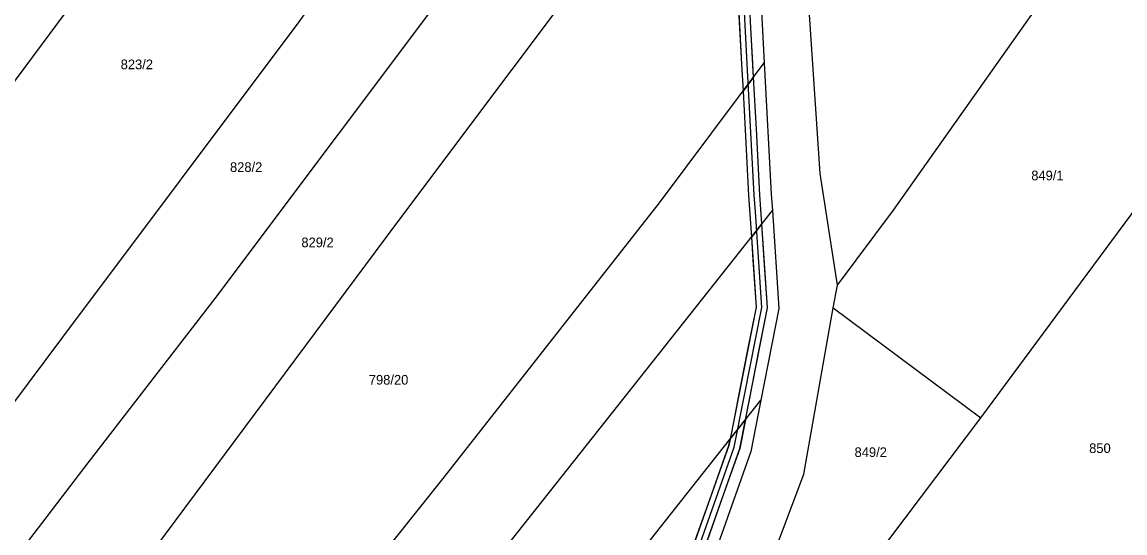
# Model space of a CAD drawing. Extents: x -7483133 to -743907, y -11317770 to -1129777.
# Drawn here: x -747703.2 to -747509.1, y -1131590 to -1131500 of the extents above; entities that cross this region are included whole.
import ezdxf

# ---------------------------------------------------------------- set-up
doc = ezdxf.new("R2010")
doc.units = 0
for name, color, linetype in [('_TRASA_vedení kabelu_CEZ', 7, 'Continuous'), ('DZ_DO_ZPF', 7, 'Continuous'), ('Hranice parcel', 7, 'Continuous'), ('hranice VB', 7, 'Continuous'), ('Parcelní čísla', 7, 'Continuous')]:
    doc.layers.add(name, color=color, linetype=linetype)

msp = doc.modelspace()

# ---------------------------------------------------------------- linework, layer by layer
at = {"layer": '_TRASA_vedení kabelu_CEZ'}
msp.add_lwpolyline([(-747606.66, -1131708.94), (-747603.52, -1131695.37), (-747628.04, -1131689.7), (-747599.97, -1131653.35), (-747599.82, -1131650.35), (-747590.15, -1131609.62), (-747577.85, -1131574.83), (-747576.11, -1131566), (-747573.02, -1131550.26), (-747574.14, -1131533.4), (-747574.33, -1131530.46), (-747575.58, -1131507.34), (-747576.38, -1131492.52)], dxfattribs=at)
at = {"layer": 'DZ_DO_ZPF'}
for points in [[(-747577.28, -1131455.8), (-747579.15, -1131458.26), (-747578.38, -1131473.06), (-747577.37, -1131492.57), (-747576.57, -1131507.4), (-747576.32, -1131512.18), (-747574.45, -1131509.68), (-747574.98, -1131499.88), (-747575.38, -1131492.47), (-747576.39, -1131472.96)], [(-747576.32, -1131512.18), (-747575.95, -1131518.96), (-747575.33, -1131530.52), (-747574.85, -1131537.87), (-747573, -1131535.54), (-747573.34, -1131530.4), (-747573.96, -1131518.84), (-747574.45, -1131509.68)], [(-747573, -1131535.54), (-747574.85, -1131537.87), (-747574.03, -1131550.19), (-747578.6, -1131573.46), (-747575.89, -1131570.02), (-747572.01, -1131550.32)], [(-747578.6, -1131573.46), (-747575.89, -1131570.02), (-747576.88, -1131575.09), (-747579.96, -1131583.79), (-747583.04, -1131592.5), (-747586.11, -1131601.2), (-747589.19, -1131609.9), (-747591.6, -1131620.05), (-747594.01, -1131630.2), (-747596.42, -1131640.34), (-747598.83, -1131650.49), (-747598.98, -1131653.55), (-747626.3, -1131689.08), (-747628.4, -1131688.54), (-747615.37, -1131671.66), (-747608.16, -1131662.32), (-747600.95, -1131652.99), (-747600.82, -1131650.21), (-747598.39, -1131639.99), (-747595.96, -1131629.77), (-747591.11, -1131609.34), (-747584.97, -1131591.95), (-747581.89, -1131583.26), (-747578.82, -1131574.56)]]:
    msp.add_lwpolyline(points, close=True, dxfattribs=at)
at = {"layer": 'Hranice parcel'}
for p, q in [((-747534.47, -1131569.66), (-747469.89, -1131482.38)), ((-747560.43, -1131550.33), (-747559.72, -1131546.32)), ((-747560.43, -1131550.33), (-747534.47, -1131569.66))]:
    msp.add_line(p, q, dxfattribs=at)
for points in [[(-747806.67, -1131645.86), (-747760.08, -1131583.56), (-747741.05, -1131557.9), (-747711.67, -1131520.04), (-747658.45, -1131448.35), (-747613.7, -1131387.55), (-747586.28, -1131353.77)], [(-747772.35, -1131654.05), (-747742.69, -1131616.2), (-747708.15, -1131571.7), (-747696.05, -1131555.49), (-747654.43, -1131499.96), (-747614.66, -1131444.39), (-747602.9, -1131429.72), (-747576.54, -1131395.88)], [(-747751.97, -1131658.69), (-747725.51, -1131622.95), (-747709.1, -1131600.51), (-747691.54, -1131577.63), (-747669.23, -1131548.64), (-747625.65, -1131490.48), (-747576.88, -1131425.52)], [(-747575.4, -1131453.35), (-747596.53, -1131480.99), (-747637.49, -1131535.62), (-747681.61, -1131594.97), (-747707.2, -1131626.86), (-747733.77, -1131662.83)], [(-747575.4, -1131453.35), (-747573.38, -1131492.36), (-747572.58, -1131507.18)], [(-747559.72, -1131546.32), (-747549.84, -1131533.09), (-747519.12, -1131489.53), (-747492.83, -1131454.72)], [(-747559.72, -1131546.32), (-747562.72, -1131526.64), (-747564.97, -1131493.37)], [(-747698.69, -1131671.28), (-747664.74, -1131625.11), (-747629.09, -1131580.38), (-747591, -1131531.84), (-747572.58, -1131507.18)], [(-747572.58, -1131507.18), (-747571.34, -1131530.28), (-747571.15, -1131533.2)], [(-747680.04, -1131675.66), (-747646.64, -1131631.19), (-747620.64, -1131595.74), (-747571.15, -1131533.2)], [(-747571.15, -1131533.2), (-747570, -1131550.45), (-747573.17, -1131566.58)], [(-747582.84, -1131630.56), (-747581.53, -1131621.85), (-747565.63, -1131579.59), (-747560.43, -1131550.33)], [(-747660.92, -1131680.14), (-747626.14, -1131633.64), (-747573.17, -1131566.58)], [(-747573.17, -1131566.58), (-747574.95, -1131575.62), (-747587.27, -1131610.47), (-747596.84, -1131650.77)], [(-747582.84, -1131630.56), (-747574.44, -1131622.7), (-747534.47, -1131569.66)]]:
    msp.add_lwpolyline(points, dxfattribs=at)
at = {"layer": 'hranice VB'}
for p, q in [((-747577.37, -1131492.57), (-747576.97, -1131499.98)), ((-747576.97, -1131499.98), (-747576.57, -1131507.4)), ((-747574.58, -1131507.29), (-747574.98, -1131499.88)), ((-747576.57, -1131507.4), (-747576.32, -1131512.18)), ((-747574.45, -1131509.68), (-747574.58, -1131507.29)), ((-747576.32, -1131512.18), (-747574.45, -1131509.68)), ((-747573.96, -1131518.84), (-747574.45, -1131509.68)), ((-747576.32, -1131512.18), (-747575.95, -1131518.96)), ((-747575.95, -1131518.96), (-747575.33, -1131530.52)), ((-747573.34, -1131530.4), (-747573.96, -1131518.84)), ((-747575.33, -1131530.52), (-747574.85, -1131537.87)), ((-747573, -1131535.54), (-747573.34, -1131530.4)), ((-747574.85, -1131537.87), (-747573, -1131535.54)), ((-747572.58, -1131541.83), (-747573, -1131535.54)), ((-747574.85, -1131537.87), (-747574.58, -1131541.83)), ((-747574.58, -1131541.83), (-747574.03, -1131550.19)), ((-747572.01, -1131550.32), (-747572.58, -1131541.83)), ((-747574.03, -1131550.19), (-747575.56, -1131558)), ((-747573.57, -1131558.26), (-747572.01, -1131550.32)), ((-747575.56, -1131558), (-747577.09, -1131565.81)), ((-747575.13, -1131566.19), (-747573.57, -1131558.26)), ((-747577.09, -1131565.81), (-747577.96, -1131570.18)), ((-747575.89, -1131570.02), (-747575.13, -1131566.19)), ((-747578.6, -1131573.46), (-747575.89, -1131570.02)), ((-747577.96, -1131570.18), (-747578.6, -1131573.46)), ((-747576.88, -1131575.09), (-747575.89, -1131570.02)), ((-747578.6, -1131573.46), (-747578.82, -1131574.56)), ((-747578.82, -1131574.56), (-747584.97, -1131591.95)), ((-747583.04, -1131592.5), (-747576.88, -1131575.09))]:
    msp.add_line(p, q, dxfattribs=at)

# ---------------------------------------------------------------- texts
at = {"layer": 'Parcelní čísla'}
for s, p in [('823/2', (-747685.84, -1131508.29)), ('828/2', (-747666.6, -1131526.38)), ('849/1', (-747525.59, -1131527.85)), ('829/2', (-747654.04, -1131539.64)), ('798/20', (-747642.17, -1131563.83)), ('849/2', (-747556.69, -1131576.58)), ('850', (-747515.4, -1131575.88))]:
    msp.add_text(s, height=1.7, dxfattribs=at).set_placement(p)

doc.saveas('drawing.dxf')
